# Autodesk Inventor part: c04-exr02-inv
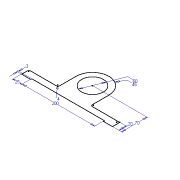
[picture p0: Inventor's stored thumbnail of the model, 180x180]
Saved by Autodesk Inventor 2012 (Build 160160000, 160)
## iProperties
Shininess: 64.0
Length Units: 11269
Angle Units: 11279
Time Units: 11290
Mass Units: 11283
Length Display Precision: 3
Angle Display Precision: 2
Compacted: True
Created: 2002-02
Part Number: c04-exr02-inv
Document SubType Name: Modeling
Density: 1 g/cm^3
Material: Default
Density: 0.0
Volumn: 0.0
Area: 0.0
PropertySet Name: Model Information
Control State: 0
Master: False
Checked Out: False
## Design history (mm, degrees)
sketch "Sketch1"
  geometry: L1 (-47.967, -16.304)-(-119.967, -16.304); L2 (-123.967, -20.304)-(-123.967, -36.304); L3 (-123.967, -36.304)-(-98.967, -36.304); L4 (-98.967, -36.304)-(-98.967, -33.304); L5 (-98.967, -33.304)-(101.033, -33.304); L6 (101.033, -33.304)-(101.033, -36.304); L7 (101.033, -36.304)-(126.033, -36.304); L8 (126.033, -36.304)-(126.033, -20.304); L9 (122.033, -16.304)-(50.033, -16.304); L10 (46.033, -12.304)-(46.033, 33.696); L11 (-43.967, 33.696)-(-43.967, -12.304); C1 r 30 at (1.033, 33.696); A1 r 45 centre (1.033, 33.696) between (46.033, 33.696) and (-43.967, 33.696); A2 r 4 centre (-47.967, -12.304) between (-47.967, -16.304) and (-43.967, -12.304); A3 r 4 centre (50.033, -12.304) between (46.033, -12.304) and (50.033, -16.304); A4 r 4 centre (122.033, -20.304) between (126.033, -20.304) and (122.033, -16.304); A5 r 4 centre (-119.967, -20.304) between (-119.967, -16.304) and (-123.967, -20.304); 1 further point
  constraints: 22 end point, 10 point on circle, 10 tangent, 8 parallel, 6 centre point, 4 equal length, 3 equal radius, 2 point on line, 1 coincident, 1 collinear, 1 horizontal, 1 perpendicular
  dimensions: "d0" = 25 distance of L2.end L3.end; "d1" = 200 distance of L4.end L5.end; "d2" = 3 distance of L3.end L4.end; "d3" = 20 distance of L7.end point (126.033, -16.304); "d4" = 70 distance from line of A1.centre L7; "d5" = 45 radius of A1; "d6" = 4 radius of A2; "d7" = 60 diameter of C1
